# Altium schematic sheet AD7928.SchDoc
size A
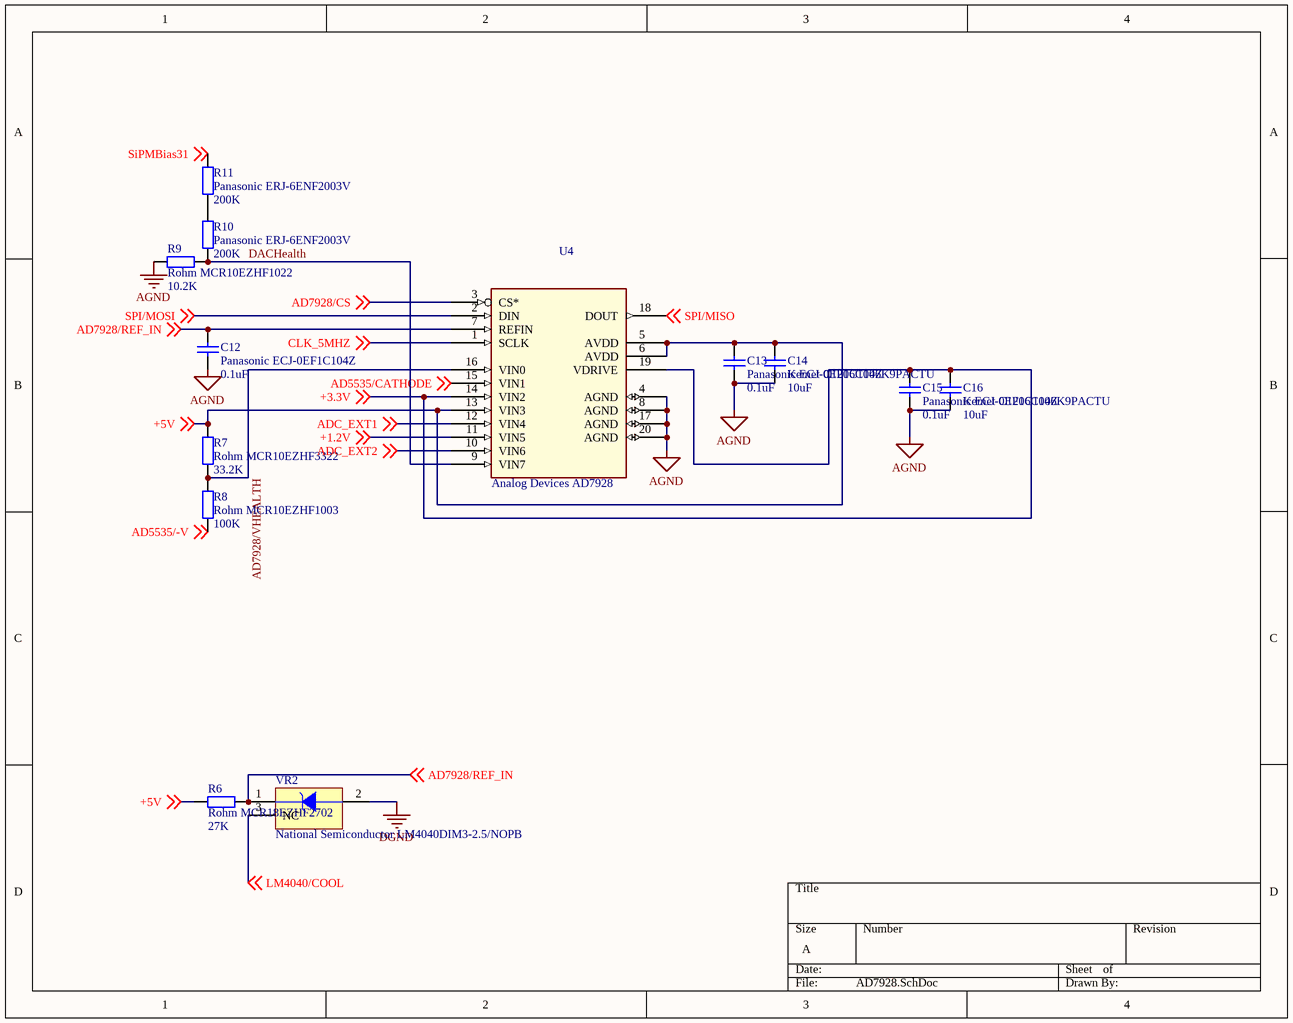
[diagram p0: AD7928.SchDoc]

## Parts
C12  Panasonic ECJ-0EF1C104Z  value 0.1uF  [0402]
C13  Panasonic ECJ-0EF1C104Z  value 0.1uF  [0402]
C14  Kemet C1206C106K9PACTU  value 10uF  [C1206]
C15  Panasonic ECJ-0EF1C104Z  value 0.1uF  [0402]
C16  Kemet C1206C106K9PACTU  value 10uF  [C1206]
R6  Rohm MCR18EZHF2702  value 27K  [3216[1206]]
R7  Rohm MCR10EZHF3322  value 33.2K  [2012[0805]]
R8  Rohm MCR10EZHF1003  value 100K  [2012[0805]]
R9  Rohm MCR10EZHF1022  value 10.2K  [2012[0805]]
R10  Panasonic ERJ-6ENF2003V  value 200K  [2012[0805]]
R11  Panasonic ERJ-6ENF2003V  value 200K  [2012[0805]]
U4  Analog Devices AD7928  [RU-20]
VR2  National Semiconductor LM4040DIM3-2.5/NOPB  [M03B]

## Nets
AGND: C12.1 C13.1 C14.1 C15.1 C16.1 R9.2 U4.4(AGND) U4.8(AGND) U4.17(AGND) U4.20(AGND)
DGND: VR2.2(V-)
+1.2V: U4.11(VIN5) ; off-sheet +1.2V
+3.3V: C15.2 C16.2 U4.14(VIN2) U4.19(VDRIVE) ; off-sheet +3.3V
+5V: C13.2 C14.2 R6.1 R7.2 U4.5(AVDD) U4.6(AVDD) U4.13(VIN3) ; off-sheet +5V
AD5535/-V: R8.1 ; off-sheet AD5535/-V
AD5535/CATHODE: U4.15(VIN1) ; off-sheet AD5535/CATHODE
AD7928/CS: U4.3(CS*) ; off-sheet AD7928/CS
AD7928/REF_IN: C12.2 R6.2 U4.7(REFIN) VR2.1(V+) ; off-sheet AD7928/REF_IN
AD7928/VHEALTH: R7.1 R8.2 U4.16(VIN0)
ADC_EXT1: U4.12(VIN4) ; off-sheet ADC_EXT1
ADC_EXT2: U4.10(VIN6) ; off-sheet ADC_EXT2
CLK_5MHZ: U4.1(SCLK) ; off-sheet CLK_5MHZ
DACHealth: R9.1 R10.1 U4.9(VIN7)
LM4040/COOL: VR2.3(NC) ; off-sheet LM4040/COOL
SiPMBias31: R11.2 ; off-sheet SiPMBias31
SPI/MISO: U4.18(DOUT) ; off-sheet SPI/MISO
SPI/MOSI: U4.2(DIN) ; off-sheet SPI/MOSI
NetR10_2: R10.2 R11.1

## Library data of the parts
C12-C16 = Cap: Capacitor
R6-R11 = Res2: Resistor
U4 = AD7928BRU-REEL7: SlotXofY: SYM 1 OF 1
VR2 = LM4040DIM3-2.5: Precision Micropower Shunt Voltage Reference; Note: Pin 3 must be left floating or connected to pin 2.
